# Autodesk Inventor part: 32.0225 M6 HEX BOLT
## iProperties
Created: 2012-10
Part Number: 32.0225 M6 HEX BOLT
Document SubType Name: Modeling
Designer: Administrator
Density: 7.85 g/cm^3
Material: Steel
Mass: 8.23571 g
Surface Area: 7.69691 cm^2
Volume: 1.04913 cm^3
Author: Administrator
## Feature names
1. Base1
